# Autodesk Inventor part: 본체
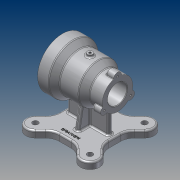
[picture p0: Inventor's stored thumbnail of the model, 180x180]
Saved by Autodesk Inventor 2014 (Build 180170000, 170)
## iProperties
Created: 2017-03
Part Number: 본체
Material: 알루미늄 6061
Document SubType Name: Modeling
Designer: Administrator
Density: 2.71 g/cm^3
Appearance: 알루미늄 - 평지
Mass: 1008.06 g
Surface Area: 842.103 cm^2
Volume: 371.977 cm^3
Author: Administrator
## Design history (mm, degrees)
sketch "스케치1"
  geometry: L1 (-50, 0)-(50, 0); L2 (-50, 35)-(-50, 45); L3 (-50, 45)-(-30, 45); L4 (-30, 45)-(-19, 36); L5 (-19, 36)-(15, 36); L6 (27, 27.5)-(50, 27.5); L7 (-50, 35)-(-27, 35); L8 (-27, 35)-(-27, 26); L9 (-27, 26)-(20, 26); L10 (20, 26)-(20, 17.5); L11 (20, 17.5)-(50, 17.5); L12 (50, 17.5)-(50, 27.5); L13 (27, 27.5)-(15, 36); 2 further points
  constraints: 26 end point, 6 parallel, 4 perpendicular, 2 vertical alignment, 1 coincident, 1 horizontal, 1 midpoint
  dimensions: "d0" = 100 distance of L1.start L1.end; "d1" = 70 diameter of L7 L1; "d2" = 90 diameter of L3 L1; "d3" = 20 distance of L2.end L3.end; "d4" = 31 horizontal distance of L2.end L4.end; "d5" = 65 distance from line of L5.end L2; "d6" = 23 distance of L6.start L6.end; "d7" = 23 distance of L2.start L7.end; "d8" = 47 distance of L8.end L9.end; "d9" = 52 diameter of L9 L1; "d10" = 35 diameter of L11 L1; "d107" = 72 diameter of L5 L1; "d108" = 55 diameter of L6 L1
revolve "회전1" sketch "스케치1" stored, may be unused: angle "d12" = 90 deg
node "작업 평면1"
sketch "스케치2"
  geometry: L1 (-45, -45)-(45, -45); L2 (45, -45)-(45, 45); L3 (45, 45)-(-45, 45); L4 (-45, 45)-(-45, -45); L5 (-45, -45)-(45, 45); L6 (45, -45)-(-45, 45); L7 (0, 0)-(-49.497, 49.497); L8 (-37.477, 61.518)-(-20.958, 45); L9 (-61.518, 37.477)-(-45, 20.958); C1 r 5 at (-49.497, 49.497); A1 r 70 centre (0, 0) between (-49.497, 49.497) and (-59.97, 36.106); A2 r 17 centre (-49.497, 49.497) between (-37.477, 61.518) and (-61.518, 37.477); 2 further points
  constraints: 18 end point, 5 point on circle, 4 midpoint, 4 parallel, 3 centre point, 3 coincident, 2 point on line, 2 tangent, 1 collinear, 1 horizontal, 1 perpendicular
  dimensions: "d14" = 90 distance of L3.end L2.end; "d15" = 90 distance of L2.end L1.end; "d16" = 140 diameter of A1; "d17" = 34 diameter of A2; "d18" = 10 diameter of C1
extrude "돌출1" join sketch "스케치2" distance "d19" = 12; taper "d20" = 0 deg
extrude "돌출2" join sketch "스케치2" distance "d21" = 12; taper "d22" = 0 deg
sketch "스케치4"
  geometry: L1 (37, -4)-(-37, -4); L2 (-37, -4)-(-37, 4); L3 (-37, 4)-(37, 4); L4 (37, 4)-(37, -4); L5 (37, -4)-(-37, 4); L6 (-37, -4)-(37, 4); 1 further point
  constraints: 12 end point, 2 midpoint, 2 parallel, 1 horizontal, 1 perpendicular
  dimensions: "d27" = 74 distance of L2.end L3.end; "d28" = 8 distance of L1.end L2.end
extrude "돌출3" join sketch "스케치4" stored distance "d29" = 12; taper "d30" = 0 deg
sketch "스케치5"
  geometry: L1 (-25, -70)-(-18.14, -31.096); L2 (18.14, -31.096)-(25, -70); L3 (-20.958, -70)-(-37.477, -70) reference; L4 (37.477, -70)-(20.958, -70) reference; 6 further points
  constraints: 4 end point, 2 point on line, 3 other
  dimensions: "d31" = 25 horizontal distance of L1.start point (0, 0); "d32" = 25 horizontal distance of L2.end point (0, 0) (= d31); "d104" = 100 deg angle of L4 L2; "d105" = 100 deg angle of L3 L1
feature "리브1" dims "d35" = 1, "d36" = 8, "d37" = 0, "d38" = 0, "d39" = 1, "d40" = 1
feature "리브2" dims "d41" = 1, "d42" = 8, "d43" = 0, "d44" = 0, "d45" = 1, "d46" = 1
sketch "스케치6"
  geometry: A1 r 27.5 centre (0, 0) between (27.5, 0) and (26.609, 6.943) reference; A2 r 7 centre (27.5, 0) between (26.609, -6.943) and (26.609, 6.943); 1 further point
  constraints: 5 point on circle, 1 centre point, 1 horizontal alignment
  dimensions: "d47" = 14 diameter of A2
extrude "돌출4" join sketch "스케치6" distance "d48" = 15; taper "d49" = 0 deg
hole "구멍1" diameter "d52" = 3.242; stored, may be unused: countersink angle "d56" = 90 deg, drill point angle "d58" = 118 deg; dims "d50" = 10, "d51" = 10, "d53" = 9, "d54" = 4, "d55" = 2, "d57" = 11
node "작업 평면2"
sketch "스케치7"
  geometry: C1 r 5 at (0, 0); 1 further point
  constraints: 1 centre point, 1 coincident
  dimensions: "d63" = 10 diameter of C1
extrude "돌출5" join sketch "스케치7" stored distance "d64" = 15; taper "d65" = 0 deg
hole "구멍2" diameter "d68" = 4.134; stored, may be unused: countersink angle "d72" = 90 deg, drill point angle "d74" = 0 deg; dims "d66" = 10, "d67" = 10, "d69" = 9, "d70" = 4, "d71" = 2, "d73" = 11
sketch "스케치8"
  geometry: 2 further points
  constraints: 1 horizontal alignment
  dimensions: "d75" = 40 distance of point (-40, 0) point (0, 0)
hole "구멍3" sketch "스케치8" at (-40, 0) diameter "d76" = 3.242; stored, may be unused: countersink angle "d80" = 90 deg, drill point angle "d82" = 118 deg; dims "d77" = 9, "d78" = 4, "d79" = 2, "d81" = 11
fillet "모깎기2" dims "d86" = 1
fillet "모깎기4" dims "d88" = 3
fillet "모깎기5" dims "d89" = 1
fillet "모깎기6" dims "d90" = 3
fillet "모깎기7" dims "d91" = 3
fillet "모깎기8" dims "d92" = 3
fillet "모깎기9" dims "d93" = 3
sketch "스케치9"
  geometry: L1 (-45, 20.958)-(-45, -20.958) reference; 2 further points
  constraints: 1 other
  dimensions: "d96" = 35 distance of point (0, 35) point (0, 0); "d106" = 45 distance from line of point (0, 35) L1
feature "엠보싱1" sketch "스케치9" dims "d14" = 90, "d15" = 90, "d16" = 140, "d17" = 34, "d18" = 10, "d97" = 0.5, "d98" = 0
chamfer "모따기1" distance "d99" = 1; stored, may be unused: second distance "d100" = 2, angle "d101" = 45 deg
fillet "모깎기11" dims "d102" = 25
fillet "모깎기12" dims "d103" = 3
node "솔리드1"
pattern_circular "원형 패턴1" dims angle "d24" = 360 deg
pattern_circular "원형 패턴2" dims angle "d60" = 360 deg
pattern_circular "원형 패턴3" dims angle "d84" = 360 deg
other parameters: "d13" = -82
